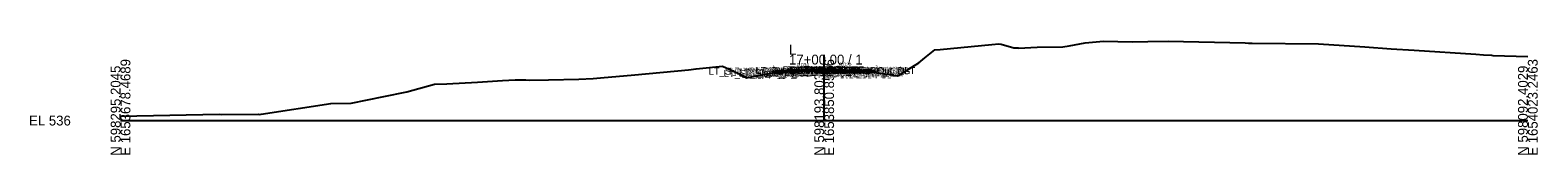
# Model space of a CAD drawing. Extents: x -26 to 403, y -10 to 6021.
# Drawn here: x -25.7 to 402.8, y 5490.3 to 5522.5 of the extents above; entities that cross this region are included whole.
import ezdxf

# ---------------------------------------------------------------- set-up
doc = ezdxf.new("R2010")
doc.units = 0
for name, color, linetype in [('Default', 7, 'Continuous'), ('Exist Cross Section Cell', 7, 'Continuous'), ('Exist XS Ground Line', 7, 'Continuous'), ('Prop CMT Pvmt Course 1', 7, 'Continuous'), ('Prop CMT Pvmt Course 1 Wedge', 7, 'Continuous'), ('Prop CMT Pvmt Course 2', 7, 'Continuous'), ('Prop CMT Pvmt Course 2 Wedge', 7, 'Continuous'), ('Prop CMT Pvmt Course 3', 7, 'Continuous'), ('Prop CMT Pvmt Surface', 7, 'Continuous'), ('Prop CMT Pvmt Surface Shoulder', 7, 'Continuous'), ('Prop CMT Pvmt Wedge Surface 1', 7, 'Continuous'), ('Prop CMT Pvmt Wedge Surface 2', 7, 'Continuous'), ('Prop CMT Pvmt Wedge Surface 3', 7, 'Continuous'), ('Prop CMT Shld Paved Course 1', 7, 'Continuous'), ('Prop CMT Shld Paved Course 2', 7, 'Continuous'), ('Prop CMT Shld Paved Course 3', 7, 'Continuous'), ('Prop CMT Slope Grass', 7, 'Continuous'), ('Prop CMT Subgrade Earthwork', 7, 'Continuous'), ('Prop XS Earthwork Shape', 7, 'Continuous'), ('Prop XS SE Text', 7, 'Continuous'), ('Prop XS Side Slope Text', 7, 'Continuous')]:
    doc.layers.add(name, color=color, linetype=linetype)

msp = doc.modelspace()

# ---------------------------------------------------------------- linework, layer by layer
at = {"layer": 'Exist Cross Section Cell'}
for p, q in [((200, 5500), (200, 5518.73)), ((0, 5500), (200, 5500)), ((200, 5500), (400, 5500))]:
    msp.add_line(p, q, dxfattribs=at)
at = {"layer": 'Exist XS Ground Line'}
msp.add_lwpolyline([(0, 5501.24), (28.04, 5501.79), (28.75, 5501.77), (39.15, 5501.79), (39.58, 5501.76), (39.98, 5501.8), (59.78, 5504.88), (65.55, 5504.97), (74.8, 5506.83), (81.38, 5508.13), (89.2, 5510.33), (92.71, 5510.48), (101.5, 5510.88), (108.55, 5511.38), (112.18, 5511.53), (115.18, 5511.58), (116.34, 5511.47), (121.59, 5511.58), (130.22, 5511.8), (134.3, 5511.93), (136.38, 5512.12), (146.18, 5513.02), (161.45, 5514.38), (163.57, 5514.67), (171.06, 5515.45), (176.46, 5512.99), (177.92, 5512.19), (179.87, 5512.57), (188.17, 5514.04), (191.57, 5514.16), (199.95, 5514.42), (200, 5514.42), (208.56, 5514.14), (211.99, 5514.06), (212.8, 5513.97), (213.66, 5513.8), (219.39, 5512.99), (220.07, 5512.85), (220.87, 5512.71), (221.14, 5512.77), (224.91, 5515.17), (226.85, 5516.4), (228.56, 5517.79), (231.45, 5520.11), (232.97, 5520.22), (247.69, 5521.6), (249.59, 5521.78), (250.27, 5521.71), (253.9, 5520.71), (255.13, 5520.67), (255.26, 5520.6), (260.51, 5520.82), (267.84, 5520.95), (269.62, 5521.23), (274.19, 5522.06), (279.34, 5522.52), (287.53, 5522.35), (291.99, 5522.51), (297.73, 5522.52), (319.65, 5522.05), (320.61, 5522.03), (321.66, 5522.02), (340.48, 5521.77), (353.66, 5520.95), (361.18, 5520.42), (367.69, 5519.97), (385.23, 5518.84), (387.44, 5518.67), (389.64, 5518.56), (390.01, 5518.52), (400, 5518.18)], dxfattribs=at)
at = {"layer": 'Prop CMT Pvmt Course 1'}
for points in [[(200, 5514.55), (188, 5514.14)], [(188, 5514.14), (188, 5513.93)], [(188, 5513.93), (188.17, 5513.94)], [(188.17, 5513.94), (200, 5514.34)], [(188.17, 5513.94), (188.17, 5513.94)], [(200, 5514.34), (200, 5514.55)], [(200, 5514.55), (212, 5514.31)], [(200, 5514.34), (200, 5514.55)], [(200, 5514.34), (200, 5514.34), (200, 5514.34)], [(211.99, 5514.1), (200, 5514.34)], [(200, 5514.34), (200, 5514.34), (200, 5514.34)], [(212, 5514.1), (211.99, 5514.1)], [(211.99, 5514.1), (211.99, 5514.1)], [(212, 5514.31), (212, 5514.1)]]:
    msp.add_lwpolyline(points, dxfattribs=at)
at = {"layer": 'Prop CMT Pvmt Course 1 Wedge'}
for points in [[(211.99, 5514.06), (208.56, 5514.14), (206.07, 5514.22)], [(206.07, 5514.22), (208.56, 5514.17)], [(208.56, 5514.17), (211.99, 5514.1)], [(211.99, 5514.1), (211.99, 5514.06)]]:
    msp.add_lwpolyline(points, dxfattribs=at)
at = {"layer": 'Prop CMT Pvmt Course 2'}
for points in [[(188.17, 5513.94), (188, 5513.93)], [(188, 5513.93), (188, 5513.73)], [(188, 5513.73), (188.17, 5513.73)], [(188.17, 5513.73), (188.17, 5513.94)], [(211.99, 5513.89), (211.99, 5514.1)], [(211.99, 5514.1), (212, 5514.1)], [(212, 5513.89), (211.99, 5513.89)], [(212, 5514.1), (212, 5513.89)]]:
    msp.add_lwpolyline(points, dxfattribs=at)
at = {"layer": 'Prop CMT Pvmt Course 2 Wedge'}
for points in [[(211.99, 5514.06), (208.56, 5514.14), (206.07, 5514.22)], [(206.07, 5514.22), (208.56, 5514.17)], [(208.56, 5514.17), (211.99, 5514.1)], [(211.99, 5514.1), (211.99, 5514.06)]]:
    msp.add_lwpolyline(points, dxfattribs=at)
at = {"layer": 'Prop CMT Pvmt Course 3'}
for points in [[(188.17, 5513.73), (188, 5513.73)], [(188, 5513.73), (188, 5513.39)], [(188, 5513.39), (188.17, 5513.4)], [(188.17, 5513.4), (188.17, 5513.73)], [(211.99, 5513.89), (212, 5513.89)], [(211.99, 5513.56), (211.99, 5513.89)], [(212, 5513.56), (211.99, 5513.56)], [(212, 5513.89), (212, 5513.56)]]:
    msp.add_lwpolyline(points, dxfattribs=at)
at = {"layer": 'Prop CMT Pvmt Surface'}
for points in [[(200, 5514.55), (188, 5514.14)], [(200, 5514.55), (212, 5514.31)]]:
    msp.add_lwpolyline(points, dxfattribs=at)
at = {"layer": 'Prop CMT Pvmt Surface Shoulder'}
for points in [[(188, 5514.14), (188, 5514.14)], [(212, 5514.31), (212, 5514.31)]]:
    msp.add_lwpolyline(points, dxfattribs=at)
at = {"layer": 'Prop CMT Pvmt Wedge Surface 1'}
for points in [[(188, 5513.93), (188, 5514.14)], [(188.17, 5513.94), (188, 5513.93)], [(200, 5514.34), (188.17, 5513.94)], [(188.17, 5513.94), (188.17, 5513.94)], [(200, 5514.55), (200, 5514.34), (200, 5514.34), (200, 5514.34)], [(200, 5514.55), (200, 5514.34), (200, 5514.34), (200, 5514.34)], [(200, 5514.34), (211.99, 5514.1)], [(211.99, 5514.1), (211.99, 5514.1)], [(211.99, 5514.1), (212, 5514.1)], [(212, 5514.1), (212, 5514.31)]]:
    msp.add_lwpolyline(points, dxfattribs=at)
at = {"layer": 'Prop CMT Pvmt Wedge Surface 2'}
for points in [[(200, 5514.34), (188, 5513.93)], [(188, 5513.93), (188, 5514.14)], [(200, 5514.55), (200, 5514.34)], [(200, 5514.55), (200, 5514.34)], [(200, 5514.34), (212, 5514.1)], [(212, 5514.1), (212, 5514.31)]]:
    msp.add_lwpolyline(points, dxfattribs=at)
at = {"layer": 'Prop CMT Pvmt Wedge Surface 3'}
for points in [[(188, 5513.73), (188, 5514.14)], [(200, 5514.13), (188, 5513.73)], [(200, 5514.55), (200, 5514.13)], [(200, 5514.55), (200, 5514.13)], [(200, 5514.13), (212, 5513.89)], [(212, 5513.89), (212, 5514.31)]]:
    msp.add_lwpolyline(points, dxfattribs=at)
at = {"layer": 'Prop CMT Shld Paved Course 1'}
for points in [[(188, 5514.14), (188, 5514.14), (187.79, 5513.93)], [(187.79, 5513.93), (188, 5513.93)], [(188, 5513.93), (188, 5514.14)], [(212, 5514.31), (212, 5514.31)], [(212, 5514.31), (212.21, 5514.1)], [(212, 5514.1), (212, 5514.31)], [(212.21, 5514.1), (212, 5514.1)]]:
    msp.add_lwpolyline(points, dxfattribs=at)
at = {"layer": 'Prop CMT Shld Paved Course 2'}
for points in [[(188, 5513.93), (187.79, 5513.93), (187.57, 5513.72)], [(187.57, 5513.72), (188, 5513.73)], [(188, 5513.73), (188, 5513.93)], [(212, 5514.1), (212.21, 5514.1), (212.43, 5513.88)], [(212, 5513.89), (212, 5514.1)], [(212.43, 5513.88), (212, 5513.89)]]:
    msp.add_lwpolyline(points, dxfattribs=at)
at = {"layer": 'Prop CMT Shld Paved Course 3'}
for points in [[(188, 5513.73), (187.57, 5513.72), (187.57, 5513.72), (187.23, 5513.38)], [(187.23, 5513.38), (188, 5513.39)], [(188, 5513.39), (188, 5513.73)], [(212, 5513.89), (212.43, 5513.88)], [(212, 5513.56), (212, 5513.89)], [(212.77, 5513.54), (212, 5513.56)], [(212.43, 5513.88), (212.43, 5513.88)], [(212.43, 5513.88), (212.77, 5513.54)]]:
    msp.add_lwpolyline(points, dxfattribs=at)
at = {"layer": 'Prop CMT Slope Grass'}
for points in [[(188, 5514.14), (186.17, 5514), (185.21, 5513.52)], [(212, 5514.31), (213.99, 5514.15), (215.1, 5513.6)]]:
    msp.add_lwpolyline(points, dxfattribs=at)
at = {"layer": 'Prop CMT Subgrade Earthwork'}
for points in [[(187.23, 5513.38), (186.58, 5514.03)], [(188, 5513.39), (187.23, 5513.38)], [(188.17, 5513.4), (188, 5513.39)], [(188.17, 5513.4), (188.19, 5514.04)], [(211.99, 5513.56), (211.97, 5514.06)], [(211.99, 5513.56), (212, 5513.56)], [(212, 5513.56), (212.77, 5513.54)], [(212.77, 5513.54), (213.42, 5514.2)]]:
    msp.add_lwpolyline(points, dxfattribs=at)
at = {"layer": 'Prop XS Earthwork Shape'}
for points in [[(186.58, 5514.03), (186.17, 5514), (185.21, 5513.52), (186.81, 5513.8)], [(188, 5513.39), (187.23, 5513.38), (186.81, 5513.8), (188, 5514.01), (188, 5513.93), (188.17, 5513.94), (188.19, 5513.94), (188.17, 5513.4)], [(188, 5513.93), (188.17, 5513.94), (188.19, 5513.94), (188.19, 5514.04), (188.17, 5514.04), (188, 5514.01)], [(200, 5514.34), (200, 5514.42), (199.95, 5514.42), (191.57, 5514.16), (188.19, 5514.04), (188.19, 5513.94)], [(200, 5514.34), (200, 5514.42), (206.07, 5514.22)], [(212, 5514.1), (211.99, 5514.1), (206.07, 5514.22), (208.56, 5514.14), (211.97, 5514.06), (211.99, 5514.06), (212.8, 5513.97), (213.13, 5513.91), (213.42, 5514.2), (212, 5514.31)], [(211.99, 5513.56), (211.97, 5514.06), (211.99, 5514.06), (212.8, 5513.97), (213.13, 5513.91), (212.77, 5513.54), (212, 5513.56)], [(213.66, 5513.8), (215.1, 5513.6), (213.99, 5514.15), (213.42, 5514.2), (213.13, 5513.91)]]:
    msp.add_lwpolyline(points, close=True, dxfattribs=at)

# ---------------------------------------------------------------- texts
at = {"layer": 'Default'}
for s, height, p in [('LT_PV_EG_TestPt', 2, (180.5, 5513.24)), ('RT_PV_IEEOP_EG', 2, (188.14, 5513.42)), ('LT_PV_IEEOP_EG', 2, (188.19, 5513.42)), ('RT_PV2_IEEOP', 2, (189.91, 5513.34)), ('LT_PV2_IEEOP', 2, (189.95, 5513.34)), ('RT_PV1_IEEOP', 2, (190.47, 5513.34)), ('LT_PV1_IEEOP', 2, (190.52, 5513.34)), ('RT_PV_EG_TestPt', 2, (192.36, 5513.22)), ('PV2_PGL', 2, (193.91, 5513.34)), ('RT_Sub_Trench_Out_DLT', 2, (193.94, 5513.2)), ('PV1_PGL', 2, (194.47, 5513.55)), ('RT_PV1_OEOT', 2, (202.69, 5513.31)), ('RT_PS1_OEOP', 2, (202.76, 5513.31)), ('LT_Sub_Trench_Out_DLT', 2, (167.15, 5513.03)), ('LT_Sub_Trench_Out', 2, (171.44, 5512.38)), ('LT_PV_Sub_Tie_Out', 2, (173.13, 5513.04)), ('LT_PS3_Shelf_Out', 2, (173.56, 5512.72)), ('LT_GS_OS_CTL', 2, (175.54, 5513)), ('LT_PV_OEEOP_EG', 2, (175.72, 5513.04)), ('LT_Slope_Fill', 2, (175.73, 5512.52)), ('LT_Sub_OEEOP', 2, (177.39, 5512.4)), ('LT_PV2_OEEOP', 2, (177.48, 5512.94)), ('LT_PV3_OEEOP', 2, (177.48, 5512.73)), ('LT_PS3_OEOP', 2, (177.81, 5512.72)), ('LT_PS2_OEOP', 2, (178.02, 5512.93)), ('LT_PV1_OEEOP', 2, (178.05, 5512.94)), ('LT_Sub_OEOT', 2, (178.08, 5512.39)), ('LT_PV2_OEOT', 2, (178.17, 5512.93)), ('LT_PV3_OEOT', 2, (178.17, 5512.73)), ('LT_PV1_OEOT', 2, (178.74, 5513.14)), ('LT_PS1_OEOP', 2, (178.8, 5513.14)), ('RT_PV3_IEEOP', 2, (189.91, 5513.13)), ('LT_PV3_IEEOP', 2, (189.95, 5513.13)), ('PV3_PGL', 2, (193.91, 5513.13)), ('RT_PV_Sub_Tie_Out', 2, (196.87, 5513.06)), ('RT_Sub_Trench_Out', 2, (196.92, 5512.54)), ('RT_PS3_Shelf_Out', 2, (198.36, 5512.88)), ('RT_PV_OEEOP_EG', 2, (199.49, 5513.06)), ('RT_Sub_OEEOP', 2, (201.15, 5512.56)), ('RT_PV2_OEEOP', 2, (201.25, 5513.1)), ('RT_PV3_OEEOP', 2, (201.25, 5512.89)), ('RT_PV1_OEEOP', 2, (201.82, 5513.1)), ('RT_Sub_OEOT', 2, (202.03, 5512.56)), ('RT_PV2_OEOT', 2, (202.13, 5513.1)), ('RT_PV3_OEOT', 2, (202.13, 5512.89)), ('RT_PS2_OEOP', 2, (202.4, 5513.1)), ('RT_PS3_OEOP', 2, (202.61, 5512.88)), ('RT_GS_OS_CTL', 2, (203.31, 5513.15)), ('RT_Slope_Fill', 2, (205.57, 5512.6)), ('-', 0.0001, (0, 5500))]:
    msp.add_text(s, height=height, dxfattribs=at).set_placement(p)
at = {"layer": 'Exist Cross Section Cell'}
for s, p in [('L', (190, 5518.73)), ('17+00.00 / 1', (190, 5515.93)), ('EL 536', (-26, 5498.6))]:
    msp.add_text(s, height=2.8, dxfattribs=at).set_placement(p)
for s, p in [('N 598295.2045', (0, 5490)), ('E 1653678.4689', (2.8, 5490)), ('N 598193.8037', (200, 5490)), ('E 1653850.8576', (202.8, 5490)), ('N 598092.4029', (400, 5490)), ('E 1654023.2463', (402.8, 5490))]:
    msp.add_text(s, height=2.8, rotation=90, dxfattribs=at).set_placement(p)
at = {"layer": 'Prop XS SE Text'}
for s, rotation, p in [('0.034', 1.9473, (192.22, 5515.29)), ('0.020', 358.8542, (204.27, 5515.46))]:
    msp.add_text(s, height=1, rotation=rotation, dxfattribs=at).set_placement(p)
at = {"layer": 'Prop XS Side Slope Text'}
for rotation, p in [(26.5651, (184.65, 5514.07)), (333.4349, (214.17, 5514.9))]:
    msp.add_text('2:1', height=1, rotation=rotation, dxfattribs=at).set_placement(p)

doc.saveas('drawing.dxf')
